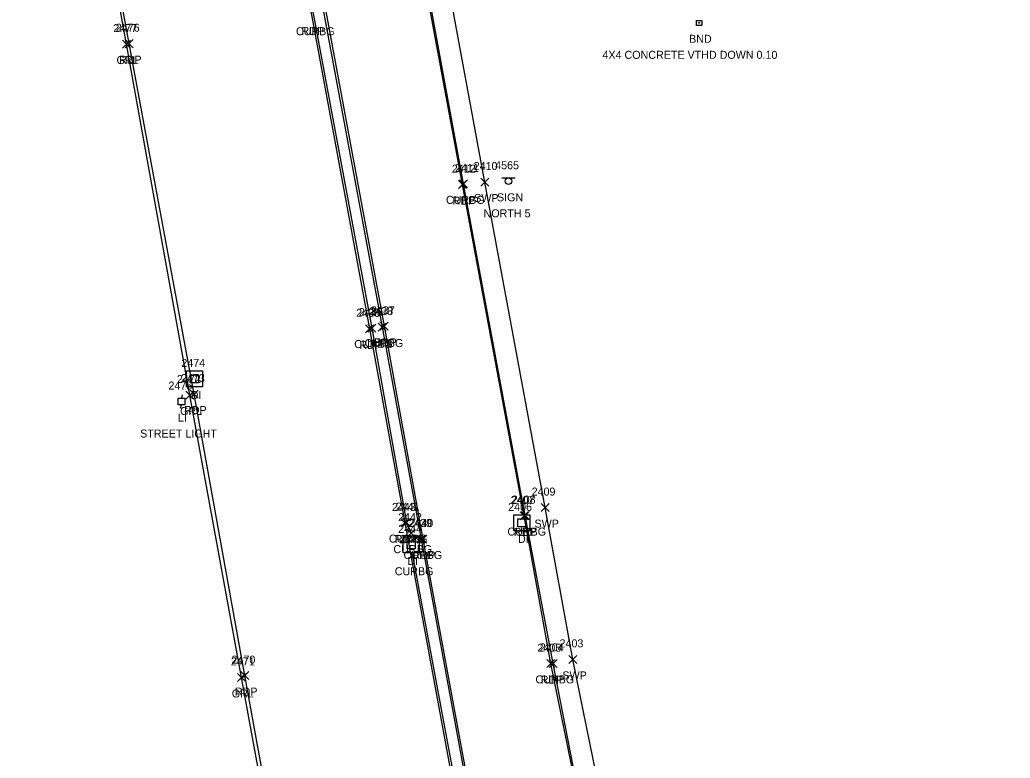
# Model space of a CAD drawing. Extents: x 1690689 to 1696275, y 438760 to 444007.
# Drawn here: x 1691271.8 to 1691519.2, y 440542 to 440726.5 of the extents above; entities that cross this region are included whole.
import ezdxf

# ---------------------------------------------------------------- set-up
doc = ezdxf.new("R2010")
doc.units = 0
for name, color, linetype in [('D_A', 7, 'Continuous'), ('D_I', 7, 'Continuous'), ('DS', 7, 'Continuous'), ('Level 18', 7, 'Continuous'), ('M_A', 7, 'Continuous'), ('M_C', 7, 'Continuous'), ('P_A', 7, 'Continuous'), ('P_I', 7, 'Continuous'), ('P_TIC', 7, 'Continuous'), ('PET', 7, 'Continuous'), ('R_A', 7, 'Continuous'), ('R_I', 7, 'Continuous'), ('R_TIC', 7, 'Continuous'), ('RC', 7, 'Continuous'), ('RGR', 7, 'Continuous'), ('RSW', 7, 'Continuous'), ('S_A', 7, 'Continuous'), ('S_C', 7, 'Continuous'), ('S_I', 7, 'Continuous'), ('SSGN', 7, 'Continuous'), ('U_A', 7, 'Continuous'), ('U_C', 7, 'Continuous'), ('U_I', 7, 'Continuous'), ('ULP', 7, 'Continuous')]:
    doc.layers.add(name, color=color, linetype=linetype)

msp = doc.modelspace()

# ---------------------------------------------------------------- linework, layer by layer
at = {"layer": 'DS'}
for p, q in [((1691313.41, 440638.74), (1691317.41, 440638.74)), ((1691313.41, 440634.74), (1691313.41, 440638.74)), ((1691314.41, 440635.74), (1691314.41, 440637.74)), ((1691314.41, 440637.74), (1691316.41, 440637.74)), ((1691315.41, 440636.74), (1691315.41, 440636.74)), ((1691315.41, 440636.74), (1691315.41, 440636.74)), ((1691316.41, 440637.74), (1691316.41, 440635.74)), ((1691317.41, 440638.74), (1691317.41, 440634.74)), ((1691317.41, 440634.74), (1691313.41, 440634.74)), ((1691316.41, 440635.74), (1691314.41, 440635.74)), ((1691395.17, 440602.78), (1691399.17, 440602.78)), ((1691395.17, 440598.78), (1691395.17, 440602.78)), ((1691399.17, 440602.78), (1691399.17, 440598.78)), ((1691396.17, 440599.78), (1691396.17, 440601.78)), ((1691396.17, 440601.78), (1691398.17, 440601.78)), ((1691398.17, 440599.78), (1691396.17, 440599.78)), ((1691397.18, 440600.78), (1691397.18, 440600.78)), ((1691397.18, 440600.78), (1691397.18, 440600.78)), ((1691398.17, 440601.78), (1691398.17, 440599.78)), ((1691367.54, 440597.29), (1691371.54, 440597.29)), ((1691367.54, 440593.29), (1691367.54, 440597.29)), ((1691371.54, 440597.29), (1691371.54, 440593.29)), ((1691399.17, 440598.78), (1691395.17, 440598.78)), ((1691368.54, 440594.29), (1691368.54, 440596.29)), ((1691368.54, 440596.29), (1691370.54, 440596.29)), ((1691369.55, 440595.29), (1691369.55, 440595.29)), ((1691369.55, 440595.29), (1691369.55, 440595.29)), ((1691370.54, 440596.29), (1691370.54, 440594.29)), ((1691371.54, 440593.29), (1691367.54, 440593.29)), ((1691370.54, 440594.29), (1691368.54, 440594.29))]:
    msp.add_line(p, q, dxfattribs=at)
at = {"layer": 'Level 18'}
msp.add_lwpolyline([(1691440.86, 440726.36), (1691442.11, 440726.36), (1691442.11, 440725.11), (1691440.86, 440725.11)], close=True, dxfattribs=at)
msp.add_circle((1691441.48, 440725.74), 0.0833, dxfattribs=at)
at = {"layer": 'P_TIC'}
for points in [[(1691298.08, 440719.53), (1691300.08, 440721.53)], [(1691300.08, 440719.53), (1691298.08, 440721.53)], [(1691381.41, 440684.3), (1691383.41, 440686.3)], [(1691383.41, 440684.3), (1691381.41, 440686.3)], [(1691358.12, 440648.27), (1691360.12, 440650.27)], [(1691360.12, 440648.27), (1691358.12, 440650.27)], [(1691361.78, 440648.9), (1691363.78, 440650.9)], [(1691363.78, 440648.9), (1691361.78, 440650.9)], [(1691314.34, 440631.97), (1691316.34, 440633.97)], [(1691316.34, 440631.97), (1691314.34, 440633.97)], [(1691396.74, 440601.52), (1691398.74, 440603.52)], [(1691398.74, 440601.52), (1691396.74, 440603.52)], [(1691367.01, 440599.75), (1691369.01, 440601.75)], [(1691369.01, 440599.75), (1691367.01, 440601.75)], [(1691371.44, 440595.72), (1691373.44, 440597.72)], [(1691373.44, 440595.72), (1691371.44, 440597.72)], [(1691403.42, 440564.6), (1691405.42, 440566.6)], [(1691405.42, 440564.6), (1691403.42, 440566.6)], [(1691327.03, 440561.61), (1691329.03, 440563.61)], [(1691329.03, 440561.61), (1691327.03, 440563.61)]]:
    msp.add_lwpolyline(points, dxfattribs=at)
at = {"layer": 'PET'}
for points in [[(1691552.42, 440436.47), (1691508.96, 440428.4), (1691494.48, 440424.84), (1691487.53, 440422.16), (1691479.98, 440421.74), (1691470.17, 440422.5), (1691465.43, 440423.73), (1691457.75, 440426.39), (1691450.59, 440430.36), (1691444.98, 440434.77), (1691439.4, 440439.84), (1691432.83, 440448.46), (1691425.81, 440467.29), (1691416.92, 440505.6), (1691412.15, 440527.64), (1691404.42, 440565.6), (1691397.74, 440602.52), (1691382.41, 440685.3), (1691370.31, 440750.54), (1691330.06, 440958.54), (1691316.82, 441030.69), (1691309.01, 441068.57), (1691294.14, 441127.58)], [(1691350.23, 440434.31), (1691349.02, 440445.67), (1691341.53, 440488.54), (1691328.03, 440562.61), (1691315.34, 440632.97), (1691299.08, 440720.53), (1691280.68, 440820.26), (1691274.23, 440854.76)], [(1691327.11, 440842.3), (1691343.83, 440752.44), (1691362.78, 440649.9), (1691372.44, 440596.72), (1691388.92, 440507.28), (1691399.19, 440450.17), (1691407.2, 440406.4), (1691406.31, 440404.65), (1691404.52, 440404.92)], [(1691315.38, 440840.77), (1691339.16, 440752.24), (1691344.67, 440727.73), (1691359.12, 440649.27), (1691368.01, 440600.75), (1691385.38, 440506.23), (1691396.38, 440445.66), (1691403.64, 440405.97), (1691404.52, 440404.92)]]:
    msp.add_lwpolyline(points, dxfattribs=at)
at = {"layer": 'R_TIC'}
for points in [[(1691297.42, 440719.43), (1691299.42, 440721.43)], [(1691299.42, 440719.43), (1691297.42, 440721.43)], [(1691381.66, 440684.49), (1691383.66, 440686.49)], [(1691383.66, 440684.49), (1691381.66, 440686.49)], [(1691386.94, 440684.95), (1691388.94, 440686.95)], [(1691388.94, 440684.95), (1691386.94, 440686.95)], [(1691358.75, 440648.46), (1691360.75, 440650.46)], [(1691360.75, 440648.46), (1691358.75, 440650.46)], [(1691361.34, 440648.71), (1691363.34, 440650.71)], [(1691363.34, 440648.71), (1691361.34, 440650.71)], [(1691313.3, 440631.73), (1691315.3, 440633.73)], [(1691315.3, 440631.73), (1691313.3, 440633.73)], [(1691401.99, 440603.6), (1691403.99, 440605.6)], [(1691403.99, 440603.6), (1691401.99, 440605.6)], [(1691397.01, 440601.6), (1691399.01, 440603.6)], [(1691399.01, 440601.6), (1691397.01, 440603.6)], [(1691367.41, 440599.85), (1691369.41, 440601.85)], [(1691369.41, 440599.85), (1691367.41, 440601.85)], [(1691368.54, 440597.21), (1691370.54, 440599.21)], [(1691370.54, 440597.21), (1691368.54, 440599.21)], [(1691371.07, 440595.75), (1691373.07, 440597.75)], [(1691373.07, 440595.75), (1691371.07, 440597.75)], [(1691368.88, 440591.69), (1691370.88, 440593.69)], [(1691370.88, 440591.69), (1691368.88, 440593.69)], [(1691408.95, 440565.67), (1691410.95, 440567.67)], [(1691410.95, 440565.67), (1691408.95, 440567.67)], [(1691404.01, 440564.67), (1691406.01, 440566.67)], [(1691406.01, 440564.67), (1691404.01, 440566.67)], [(1691326.21, 440561.16), (1691328.21, 440563.16)], [(1691328.21, 440561.16), (1691326.21, 440563.16)]]:
    msp.add_lwpolyline(points, dxfattribs=at)
at = {"layer": 'RC'}
for points in [[(1691450.76, 440430.58), (1691444.92, 440435.07), (1691439.78, 440439.75), (1691432.93, 440448.9), (1691426.12, 440467.24), (1691417.19, 440505.54), (1691412.4, 440527.61), (1691405.01, 440565.67), (1691398.01, 440602.6), (1691382.66, 440685.49), (1691370.67, 440750.86), (1691351.95, 440846.96), (1691330.25, 440958.42), (1691317.04, 441030.78), (1691309.36, 441068.61), (1691294.46, 441127.62), (1691280.16, 441186.14), (1691271.8, 441225.57)], [(1691326.44, 440842.32), (1691343.27, 440752.33), (1691362.34, 440649.71), (1691372.07, 440596.75), (1691388.57, 440507.07), (1691399.02, 440450.03), (1691406.75, 440406.47), (1691406.03, 440405.14), (1691404.87, 440405.37)], [(1691316.03, 440841.06), (1691339.83, 440752.04), (1691345.19, 440727.63), (1691359.75, 440649.46), (1691368.41, 440600.85), (1691369.54, 440598.21)], [(1691369.88, 440592.69), (1691385.96, 440506.35), (1691395.57, 440453.11), (1691397.57, 440451.5), (1691398.07, 440448.42), (1691396.76, 440445.61), (1691404.32, 440406.1), (1691404.87, 440405.37)]]:
    msp.add_lwpolyline(points, dxfattribs=at)
at = {"layer": 'RGR'}
msp.add_lwpolyline([(1691349.43, 440432.67), (1691348.1, 440445.44), (1691340.7, 440488.56), (1691327.21, 440562.16), (1691314.3, 440632.73), (1691298.42, 440720.43), (1691280.26, 440820.33), (1691273.69, 440854.21)], dxfattribs=at)
at = {"layer": 'RSW'}
msp.add_lwpolyline([(1691443.18, 440443.49), (1691437.15, 440451.8), (1691431.59, 440467.18), (1691422.3, 440506.42), (1691417.59, 440529.04), (1691409.95, 440566.67), (1691402.99, 440604.6), (1691387.94, 440685.95), (1691375.88, 440751.37), (1691356.89, 440847.96), (1691335.56, 440959.35), (1691322.05, 441031.91), (1691314.28, 441069.9), (1691299.65, 441129.23)], dxfattribs=at)
at = {"layer": 'SSGN'}
for p, q in [((1691392.21, 440687), (1691395.54, 440687)), ((1691393.86, 440686.16), (1691393.86, 440686.16))]:
    msp.add_line(p, q, dxfattribs=at)
msp.add_circle((1691393.86, 440686.16), 0.833, dxfattribs=at)
at = {"layer": 'ULP'}
for p, q in [((1691311.36, 440630.26), (1691311.36, 440631.93)), ((1691311.36, 440631.93), (1691313.03, 440631.93)), ((1691312.36, 440632.76), (1691312.19, 440631.93)), ((1691313.03, 440631.93), (1691313.03, 440630.26)), ((1691313.03, 440630.26), (1691311.36, 440630.26)), ((1691311.94, 440629.43), (1691312.19, 440630.26)), ((1691312.19, 440631.1), (1691312.19, 440631.1))]:
    msp.add_line(p, q, dxfattribs=at)

# ---------------------------------------------------------------- texts
at = {"layer": 'D_A'}
for p in [(1691314.47, 440631.74), (1691396.23, 440595.78), (1691368.6, 440590.29)]:
    msp.add_text('DI', height=2, dxfattribs=at).set_placement(p)
at = {"layer": 'D_I'}
for s, p in [('2474', (1691312.15, 440639.74)), ('2406', (1691393.78, 440603.78)), ('2444', (1691366.29, 440598.29))]:
    msp.add_text(s, height=2, dxfattribs=at).set_placement(p)
at = {"layer": 'M_A'}
msp.add_text('BND', height=2, dxfattribs=at).set_placement((1691438.97, 440720.74))
at = {"layer": 'M_C'}
msp.add_text('4X4 CONCRETE VTHD DOWN 0.10', height=2, dxfattribs=at).set_placement((1691417.33, 440716.74))
at = {"layer": 'P_A'}
for p in [(1691342.16, 440722.73), (1691296.57, 440715.53), (1691379.89, 440680.3), (1691360.27, 440644.9), (1691356.6, 440644.27), (1691312.83, 440627.97), (1691395.22, 440597.52), (1691365.5, 440595.75), (1691369.93, 440591.72), (1691401.91, 440560.6), (1691325.52, 440557.61)]:
    msp.add_text('RDP', height=2, dxfattribs=at).set_placement(p)
at = {"layer": 'P_I'}
for s, p in [('2476', (1691295.77, 440723.53)), ('2412', (1691379.71, 440688.3)), ('2436', (1691355.8, 440652.27)), ('2437', (1691359.52, 440652.9)), ('2473', (1691312.08, 440635.97)), ('2407', (1691394.4, 440605.52)), ('2443', (1691364.75, 440603.75)), ('2440', (1691369.09, 440599.72)), ('2405', (1691401.08, 440568.6)), ('2470', (1691324.68, 440565.61))]:
    msp.add_text(s, height=2, dxfattribs=at).set_placement(p)
at = {"layer": 'R_A'}
for s, p in [('CURBG', (1691340.77, 440722.63)), ('GRL', (1691295.96, 440715.43)), ('CURBG', (1691378.24, 440680.49)), ('SWP', (1691385.3, 440680.95)), ('CURBG', (1691357.92, 440644.71)), ('CURBG', (1691355.33, 440644.46)), ('GRL', (1691311.84, 440627.73)), ('CURBG', (1691393.59, 440597.6)), ('SWP', (1691400.35, 440599.6)), ('CURBG', (1691363.99, 440595.85)), ('CURBG', (1691365.12, 440593.21)), ('CURBG', (1691367.65, 440591.75)), ('CURBG', (1691365.46, 440587.69)), ('CURBG', (1691400.59, 440560.67)), ('SWP', (1691407.32, 440561.67)), ('GRL', (1691324.75, 440557.16))]:
    msp.add_text(s, height=2, dxfattribs=at).set_placement(p)
at = {"layer": 'R_I'}
for s, p in [('2477', (1691295.16, 440723.43)), ('2411', (1691380.53, 440688.49)), ('2410', (1691385.16, 440688.95)), ('2435', (1691356.49, 440652.46)), ('2438', (1691359.08, 440652.71)), ('2472', (1691311.04, 440635.73)), ('2409', (1691399.64, 440607.6)), ('2408', (1691394.67, 440605.6)), ('2441', (1691365.72, 440603.85)), ('2442', (1691366.28, 440601.21)), ('2439', (1691368.8, 440599.75)), ('2445', (1691366.62, 440595.69)), ('2404', (1691401.67, 440568.67)), ('2403', (1691406.61, 440569.67)), ('2471', (1691324.52, 440565.16))]:
    msp.add_text(s, height=2, dxfattribs=at).set_placement(p)
at = {"layer": 'S_A'}
msp.add_text('SIGN', height=2, dxfattribs=at).set_placement((1691390.99, 440681.14))
at = {"layer": 'S_C'}
msp.add_text('NORTH 5', height=2, dxfattribs=at).set_placement((1691387.63, 440677.14))
at = {"layer": 'S_I'}
msp.add_text('4565', height=2, dxfattribs=at).set_placement((1691390.53, 440689.14))
at = {"layer": 'U_A'}
msp.add_text('LI', height=2, dxfattribs=at).set_placement((1691311.3, 440626.1))
at = {"layer": 'U_C'}
msp.add_text('STREET LIGHT', height=2, dxfattribs=at).set_placement((1691301.86, 440622.1))
at = {"layer": 'U_I'}
msp.add_text('2475', height=2, dxfattribs=at).set_placement((1691308.93, 440634.1))

doc.saveas('drawing.dxf')
